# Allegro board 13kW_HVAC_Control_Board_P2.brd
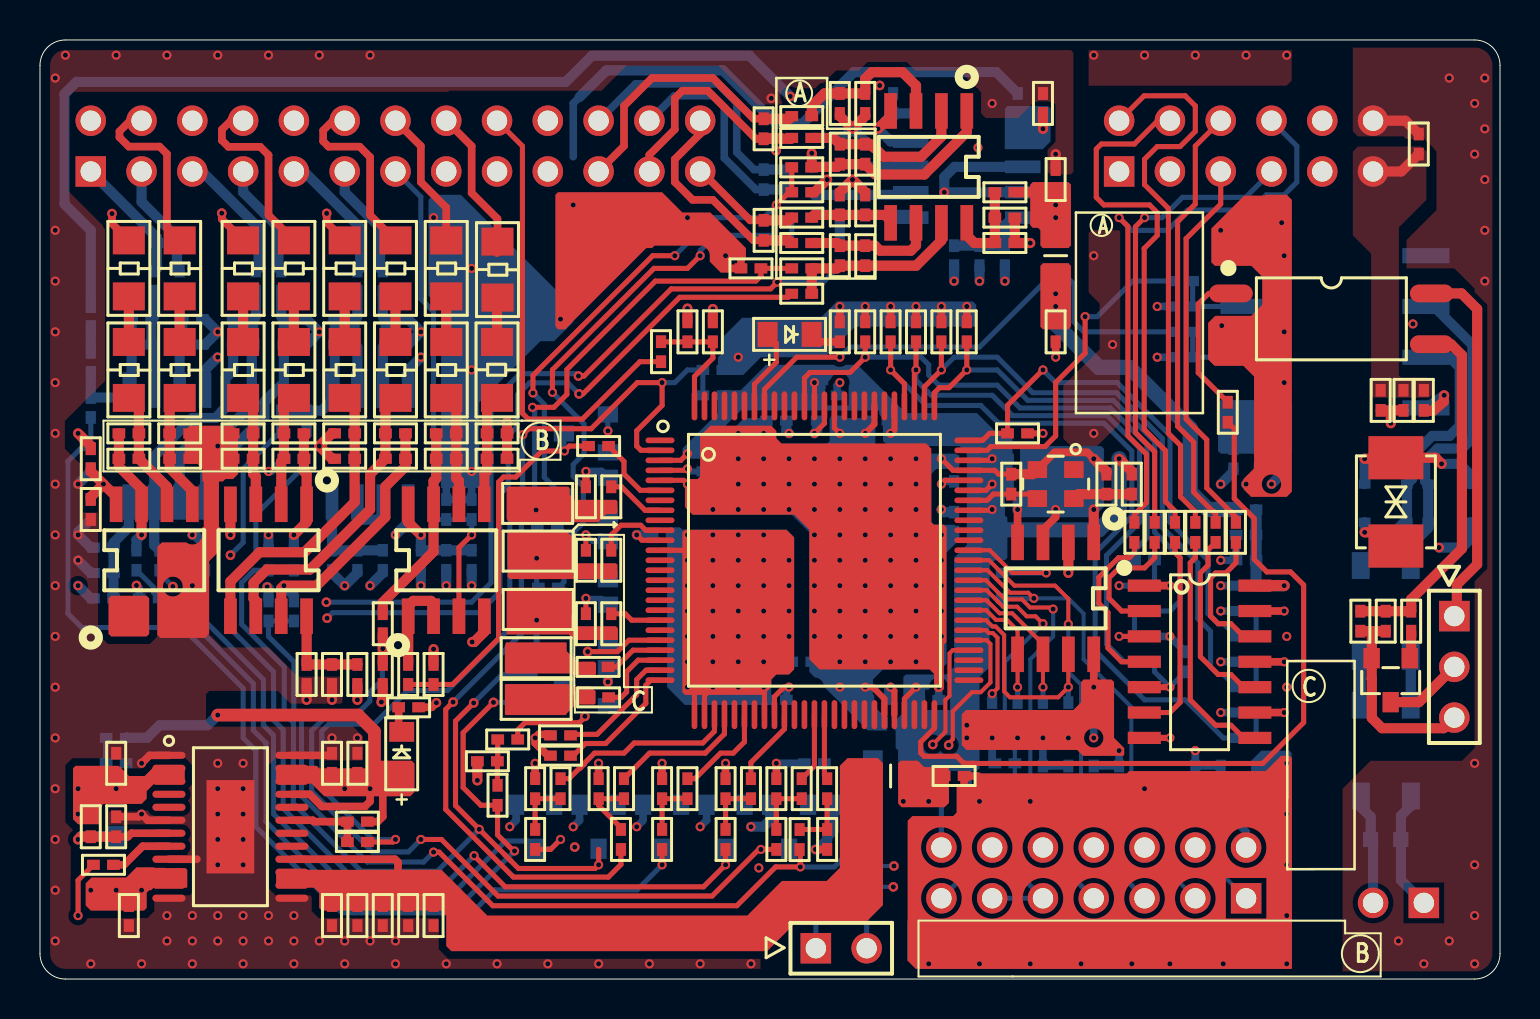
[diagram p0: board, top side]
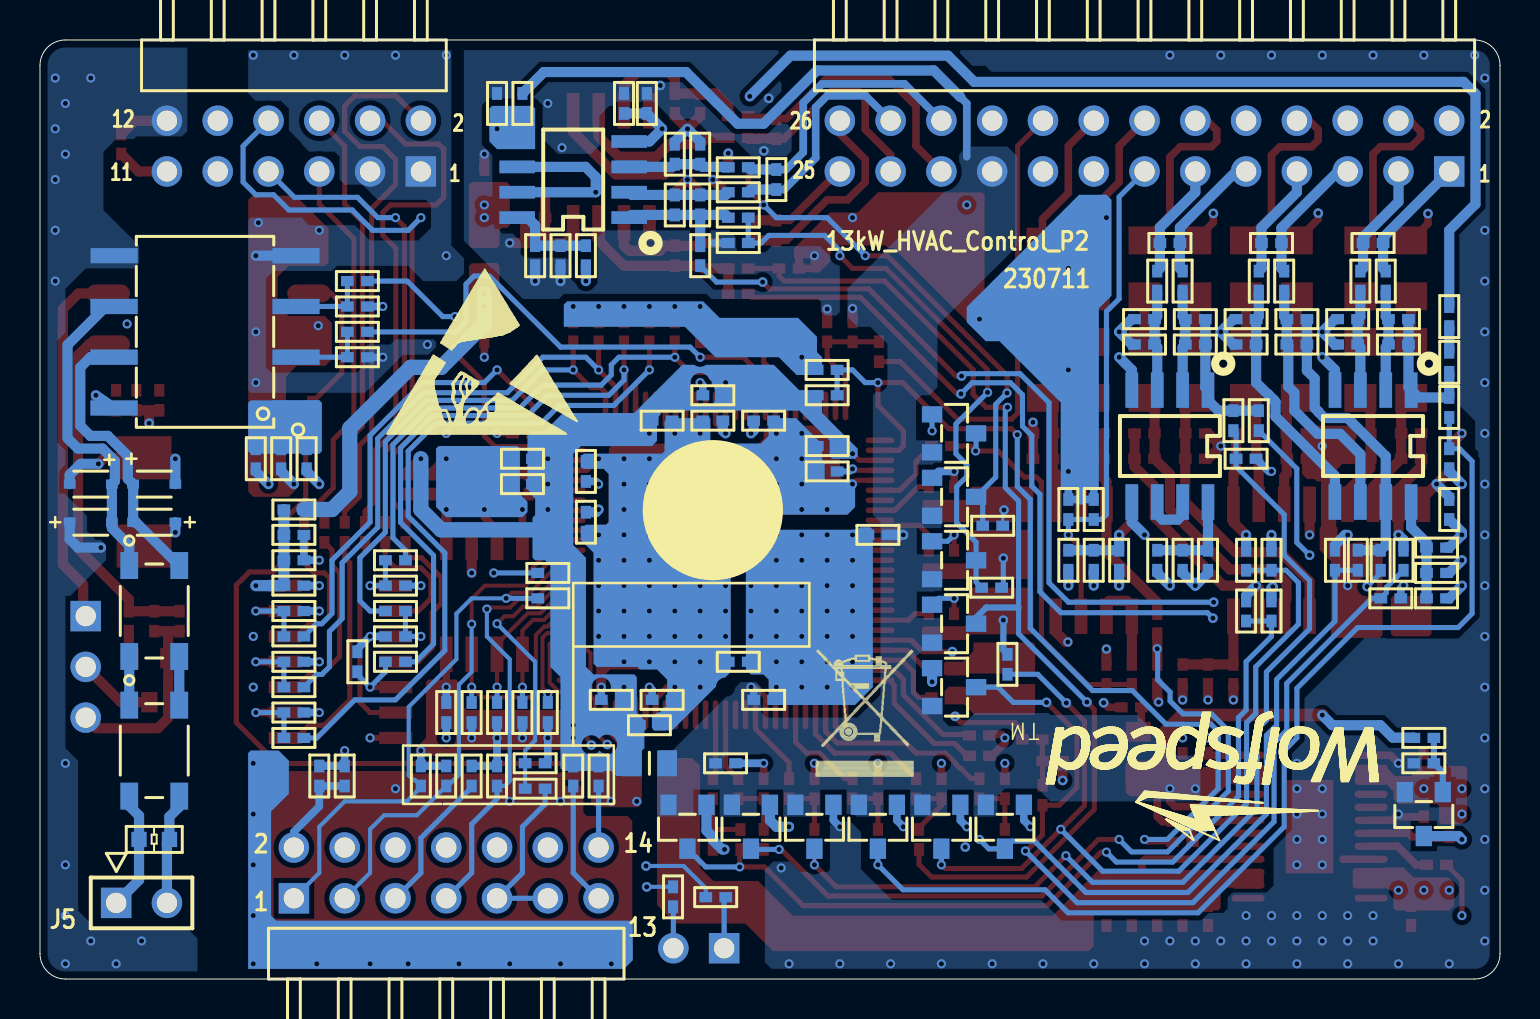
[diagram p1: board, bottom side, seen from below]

Outline 73.03 x 46.99 mm; copper layers: TOP, GND02, GND03, BOTTOM. Coordinates in mm from the lower left corner of the outline.
Outline path: 0,45.72 arc(0.37,46.62) 1.27,46.99 71.75,46.99 arc(72.65,46.62) 73.03,45.72 73.03,1.27 arc(72.65,0.37) 71.75,0 1.27,0 arc(0.37,0.37) 0,1.27 0,45.72

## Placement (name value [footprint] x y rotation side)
C1  10u  [C0402]  45.72 22.86 90 bottom
C2  10u  [C0402]  36.83 27.94 0 bottom
C3  0.1u  [C0402]  39.37 27.94 180 bottom
C4  0.1u  [C0402]  33.66 25.4 180 bottom
C5  0.1u  [C0402]  41.91 13.97 0 bottom
C6  0.1u  [C0402]  45.72 25.4 270 bottom
C7  2.2u  [C0402]  31.11 22.23 0 bottom
C8  2.2u  [C0402]  36.83 13.97 180 bottom
C9  10u  [C0402]  39.37 29.21 0 bottom
C10  0.1u  [C0402]  33.66 26.67 0 bottom
C11  0.1u  [C0402]  41.91 27.94 180 bottom
C12  0.1u  [C0402]  48.9 24.77 0 bottom
C13  0.1u  [C0402]  44.45 13.97 0 bottom
C14  2.2u  [C0402]  48.9 26.04 0 bottom
C15  22n  [C0402]  33.66 30.48 0 bottom
C16  0.1u  [C0402]  14.61 10.79 90 top
C17  10u  [C0402]  15.88 10.79 90 top
C18  10u  [C0402]  14.61 3.17 270 top
C19  0.1u  [C0402]  59.05 10.16 270 bottom
C20  10u  [C0402]  15.88 3.17 270 top
C21  0.1u  [C0402]  18.41 3.17 270 top
C22  0.1u  [C0402]  17.14 3.17 270 top
C23  10u  [C0402]  4.45 3.17 270 top
C24  10u  [C0402]  3.81 10.8 90 top
C25  0.1u  [C0402]  3.81 7.62 90 top
C26  0.1u  [C0402]  52.7 13.34 270 bottom
C27  2.2u  [C0402]  53.34 24.77 90 top
C28  22p  [C0402]  48.58 24.77 90 top
C29  10u  [C0402]  42.55 12.7 180 bottom
C30  10u  [C0402]  19.68 3.17 270 top
C31  10u  [C0402]  38.73 10.79 180 bottom
C32  0.1u  [C0402]  45.72 10.16 0 top
C33  10u  [C0402]  50.8 40.01 90 top
C34  10u  [C0402]  50.8 32.38 270 top
C35  120p  [C0402]  67.31 17.91 270 top
C36  0.1u  [C0402]  3.17 21.59 180 bottom
C37  2.2n  [C0402]  2.54 26.04 270 bottom
C38  330p  [C0402]  5.08 31.75 0 bottom
C39  2.2n  [C0402]  8.26 20.95 90 bottom
C40  330p  [C0402]  10.16 33.02 0 bottom
C41  2.2n  [C0402]  17.14 15.24 270 top
C42  330p  [C0402]  22.86 26.04 180 top
C43  330p  [C0402]  20.32 26.04 0 top
C44  330p  [C0402]  7.62 31.75 180 bottom
C45  330p  [C0402]  12.7 31.75 180 bottom
C46  1u  [C0402]  20.32 23.5 270 bottom
C47  0.01u  [C0402]  19.68 15.24 90 top
C48  330p  [C0402]  15.24 31.75 0 bottom
C49  2.2n  [C0402]  12.7 26.04 180 bottom
C50  0.1u  [C0402]  14.61 20.95 270 bottom
C51  330p  [C0402]  17.78 31.75 180 bottom
C52  0.47u  [C0402]  50.16 43.81 90 top
C53  0.1u  [C0402]  2.54 23.5 270 bottom
C54  330p  [C0402]  6.99 26.04 180 top
C55  0.01u  [C0402]  68.2 28.96 270 top
C56  2.2n  [C0402]  5.46 19.05 180 bottom
C57  0.1u  [C0402]  67.06 28.96 270 top
C58  1u  [C0402]  68.96 41.78 90 top
C59  330p  [C0402]  4.45 26.04 180 top
C60  0.1u  [C0402]  60.96 26.04 90 bottom
C61  1u  [C0402]  59.69 26.04 90 bottom
C62  330p  [C0402]  10.16 26.04 0 top
C63  2.2n  [C0402]  11.43 20.95 90 bottom
C64  120p  [C0402]  57.15 31.11 180 bottom
C65  120p  [C0402]  57.15 33.66 180 bottom
C66  330p  [C0402]  12.7 26.04 0 top
C67  330p  [C0402]  15.24 26.04 0 top
C68  0.1u  [C0402]  14.61 15.24 270 top
C69  2.2n  [C0402]  11.43 18.41 90 bottom
C70  330p  [C0402]  17.78 26.04 0 top
C71  NA  [C0402]  60.33 13.34 180 bottom
C72  NA  [C0402]  60.33 15.88 180 bottom
C73  NA  [C0402]  60.33 18.41 180 bottom
C74  NA  [C0402]  55.24 19.68 180 bottom
C75  NA  [C0402]  55.24 17.14 0 bottom
C76  NA  [C0402]  57.15 15.88 90 bottom
C77  1u  [C0402]  60.33 19.68 180 bottom
C78  0.1u  [C0402]  60.33 22.23 180 bottom
C79  0.01u  [C0402]  60.33 20.95 180 bottom
C80  2.2n  [C0402]  36.83 9.53 90 top
C81  NA  [C0402]  27.3 20.95 90 top
C82  2.2u  [C0402]  26.04 12.19 180 top
C83  2.2u  [C0402]  26.04 11.18 180 top
C84  2.2n  [C0402]  22.38 10.9 180 top
C85  NA  [C0402]  27.94 9.53 90 top
C86  2.2n  [C0402]  27.3 17.78 90 top
C87  2.2n  [C0402]  39.37 6.99 270 top
C88  NA  [C0402]  27.3 24.13 90 top
C89  4.7u  [C0402]  20.32 20.95 270 bottom
C90  330p  [C0402]  33.66 32.38 90 top
C91  4.7u  [C0402]  3.17 20.32 0 bottom
C92  4.7u  [C0402]  15.88 20.95 270 bottom
C93  4.7u  [C0402]  2.54 23.5 270 top
C94  47p  [C0402]  41.27 43.81 90 top
C95  220p  [C0402]  38.1 39.37 180 top
C96  47p  [C0402]  41.27 41.27 270 top
C97  0.1u  [C0402]  48.26 36.83 0 top
C98  47p  [C0402]  40.01 38.73 270 top
C99  4.7u  [C0402]  48.26 38.1 0 top
C100  220p  [C0402]  35.56 35.56 0 top
C101  47p  [C0402]  41.27 36.2 270 top
C102  0.1u  [C0402]  46.99 36.2 270 bottom
C103  47p  [C0402]  41.27 41.27 270 bottom
C104  4.7u  [C0402]  13.34 15.24 270 top
C105  4.7u  [C0402]  48.26 36.2 270 bottom
C106  220p  [C0402]  38.1 36.83 180 bottom
C107  47p  [C0402]  41.27 38.73 270 bottom
C108  2.2n  [C0402]  34.29 9.53 90 top
C109  2.2n  [C0402]  24.77 9.53 90 top
C110  2.2n  [C0402]  31.11 9.53 90 top
C111  0.1u  [C0402]  43.81 43.81 90 bottom
C112  0.1u  [C0402]  42.67 43.81 270 bottom
C113  0.1u  [C0402]  19.05 20.95 270 bottom
D1  SML-211UTT86  [LED0805]  37.49 32.26 0 top
D2  SML-211UTT86  [LED0805]  18.09 11.27 90 top
D3  BAS21WS-TP  [DIOD-SOD323-2-A_V]  67.31 24.77 180 bottom
D4  BAS21WS-TP  [DIOD-SOD323-2-A_V]  70.48 24.77 0 bottom
D5  BAS21WS-TP  [DIOD-SOD323-2-A_V]  67.31 22.86 0 bottom
D6  BAS21WS-TP  [DIOD-SOD323-2-A_V]  70.48 22.86 180 bottom
D7  SMBJ15CA  [DO214AA]  67.82 23.88 270 top
D8  BAV99-TP  [SOT-23-3]  27.3 27.3 270 bottom
D9  BAV99-TP  [SOT-23-3]  27.3 14.61 270 bottom
D10  BAV99-TP  [SOT-23-3]  27.94 7.62 0 bottom
D11  BAV99-TP  [SOT-23-3]  40.64 7.62 0 bottom
D12  BAV99-TP  [SOT-23-3]  31.12 7.62 0 bottom
D13  BAV99-TP  [SOT-23-3]  24.77 7.62 0 bottom
D14  BAV99-TP  [SOT-23-3]  34.29 7.62 0 bottom
D15  BAV99-TP  [SOT-23-3]  37.47 7.62 0 bottom
D16  BAV99-TP  [SOT-23-3]  27.3 24.13 270 bottom
D17  BAV99-TP  [SOT-23-3]  27.3 17.78 270 bottom
D18  BAV99-TP  [SOT-23-3]  27.3 20.95 270 bottom
DACA  Test point  [TEST_270X100_SMT]  24.82 14 0 top
DACB  Test point  [TEST_270X100_SMT]  24.82 16.08 0 top
IC1  -  [TCLT1003]  64.59 33.04 0 top
IU  Test point  [TEST_270X100_SMT]  24.89 23.8 0 top
IV  Test point  [TEST_270X100_SMT]  24.92 18.49 0 top
IW  Test point  [TEST_270X100_SMT]  24.92 21.41 0 top
J1  2*13P  [HDR2X13H-254MM-90-OP]  17.78 41.68 0 bottom
J2  2*6P  [HDR2X6H-254MM-90-OP]  60.33 41.68 0 bottom
J3  Header 3  [HDR1X3-254MM]  70.74 15.62 270 top
J4  JTAG  [HDR2X7H-254MM-90]  52.7 5.31 180 bottom
J5  CAN  [HDR1X2H-254MM]  67.94 3.81 180 top
J6  SCI  [HDR1X2H-254MM]  40.08 1.54 0 top
L1  BLM21PG221SN1D  [6-0805_L]  42.55 10.79 0 bottom
L2  BLM21PG221SN1D  [6-0805_L]  50.8 36.2 270 top
L3  BLM21PG221SN1D  [6-0805_L]  42.55 10.16 0 top
NOREF  -  []  0 1.57 0 top
NOREF#2  -  []  -4.79 0 90 top
NOREF#3  -  []  75.44 239.4 90 top
NOREF#4  -  []  231.71 47.71 0 top
NOREF#5  -  []  0 240.03 90 top
NOREF#6  -  []  -3.16 0 90 top
NOREF#7  -  []  151.56 239.13 90 top
NOREF#8  -  []  372.11 -26.07 0 top
NOREF#9  -  []  -7 4.11 0 top
NOREF#10  -  []  50.8 30.48 180 bottom
NOREF#11  -  []  31.75 13.94 180 bottom
NOREF#12  -  []  39.37 23.46 180 bottom
Q1  2N7002  [SOT-23-3]  3.81 8.26 0 bottom
Q2  FMMTL619TA  [SOT-23-3]  67.56 14.96 180 top
R1  2k  [0402]  42.55 32.38 270 top
R2  2k  [0402]  43.81 32.38 270 top
R3  2k  [0402]  45.09 32.38 270 top
R4  2k  [0402]  46.35 32.38 270 top
R5  2k  [0402]  48.9 27.3 180 top
R6  2k  [0402]  41.27 32.38 270 top
R7  2k  [0402]  47.62 20.32 180 bottom
R8  2k  [0402]  47.62 13.34 270 bottom
R9  10k  [0402]  33.66 29.21 0 bottom
R10  2k  [0402]  47.62 19.05 180 bottom
R11  10K  [0402]  2.54 7.62 90 top
R12  100K  [0402]  15.88 7.87 180 top
R13  0  [0402]  15.88 6.86 180 top
R14  0  [0402]  3.17 5.71 0 top
R15  1.5K  [0402]  3.81 12.06 0 bottom
R16  0  [0402]  57.78 10.16 270 bottom
R17  10k  [0402]  53.98 10.16 90 bottom
R18  12K  [0402]  3.81 10.79 180 bottom
R19  10k  [0402]  52.7 10.16 90 bottom
R20  0  [0402]  51.44 10.16 90 bottom
R21  10k  [0402]  50.16 10.16 90 bottom
R22  10k  [0402]  48.26 10.79 180 bottom
R23  2k  [0402]  45.09 10.16 270 bottom
R24  0  [0402]  48.26 9.53 0 bottom
R25  2k  [0402]  46.35 10.16 270 bottom
R26  10  [0402]  54.61 24.77 270 top
R27  2k  [0402]  40.01 32.38 270 top
R28  2k  [0402]  18.44 13.6 180 top
R29  0  [0402]  38.1 15.88 180 bottom
R30  10k  [0402]  48.9 13.34 270 bottom
R31  10k  [0402]  50.16 13.34 270 bottom
R32  10k  [0402]  51.44 13.34 270 bottom
R33  510  [0402]  59.41 28.36 90 top
R34  1k  [0402]  68.58 17.91 270 top
R35  20k  [0402]  66.04 17.91 90 top
R36  2k  [0402]  39.23 4.1 180 bottom
R37  2k  [0402]  41.36 4.11 270 bottom
R38  100  [0402]  31.06 31.39 90 top
R39  12k  [R1206]  22.86 30.48 270 top
R40  2k  [0402]  5.08 33.02 180 bottom
R41  12k  [0402]  22.86 27.3 0 top
R42  2k  [0402]  5.71 34.92 270 bottom
R43  2k  [0402]  10.16 31.75 180 bottom
R44  NA  [0402]  6.35 36.83 180 bottom
R45  12k  [0402]  20.32 27.3 180 top
R46  2k  [0402]  10.79 34.92 270 bottom
R47  0  [R1206]  20.32 35.56 90 top
R48  12k  [R1206]  20.32 30.48 90 top
R49  2k  [0402]  6.99 34.92 270 bottom
R50  NA  [0402]  11.43 36.83 180 bottom
R51  2k  [0402]  7.62 33.02 0 bottom
R52  2k  [0402]  12.06 34.92 270 bottom
R53  2k  [0402]  12.7 33.02 0 bottom
R54  100  [0402]  18.41 15.24 270 top
R55  1k  [0402]  38.1 42.09 180 top
R56  2k  [0402]  21.59 23.5 270 bottom
R57  2k  [0402]  15.24 33.02 180 bottom
R58  1k  [0402]  13.34 27.94 90 bottom
R59  2k  [0402]  15.88 34.92 270 bottom
R60  10  [0402]  17.14 20.95 270 bottom
R61  NA  [0402]  16.51 36.83 180 bottom
R62  2k  [0402]  17.14 34.92 270 bottom
R63  2k  [0402]  17.78 33.02 0 bottom
R64  NA  [0402]  2.54 30.86 270 bottom
R65  NA  [0402]  5.97 20.95 90 bottom
R66  10  [0402]  2.54 26.04 90 top
R67  1k  [0402]  4.83 20.95 90 bottom
R68  5k  [0402]  6.99 27.3 0 top
R69  100k  [R1206]  6.99 35.56 90 top
R70  5k  [R1206]  6.99 30.48 90 top
R71  100k  [R1206]  4.45 35.56 90 top
R72  5k  [R1206]  4.45 30.48 90 top
R73  10  [0402]  62.23 26.04 90 bottom
R74  5k  [0402]  4.45 27.3 0 top
R75  0  [0402]  69.22 28.96 270 top
R76  1k  [0402]  12.7 20.95 90 bottom
R77  5k  [0402]  10.16 27.3 180 top
R78  100k  [R1206]  10.16 35.56 90 top
R79  5k  [R1206]  10.16 30.48 90 top
R80  1k  [0402]  57.15 32.38 0 bottom
R81  120  [R0603]  67.31 6.99 0 bottom
R82  1k  [0402]  57.15 34.92 0 bottom
R83  100k  [R1206]  12.7 35.56 90 top
R84  5k  [R1206]  12.7 30.48 90 top
R85  5k  [0402]  12.7 27.3 180 top
R86  10  [0402]  15.88 15.24 270 top
R87  1k  [0402]  12.7 18.41 90 bottom
R88  5k  [0402]  15.24 27.3 180 top
R89  100k  [R1206]  15.24 35.56 90 top
R90  5k  [R1206]  15.24 30.48 90 top
R91  100k  [R1206]  17.78 35.56 90 top
R92  5k  [R1206]  17.78 30.48 90 top
R93  5k  [0402]  17.78 27.3 180 top
R94  68  [0402]  57.78 22.35 90 top
R95  68  [0402]  56.77 22.35 270 top
R96  1k  [0402]  60.33 12.06 0 bottom
R97  68  [0402]  58.8 22.35 90 top
R98  1k  [0402]  55.24 15.88 0 bottom
R99  1k  [0402]  60.33 14.61 0 bottom
R100  68  [0402]  54.74 22.35 270 top
R101  1k  [0402]  55.24 18.41 180 bottom
R102  68  [0402]  59.82 22.35 90 top
R103  1k  [0402]  60.33 17.14 0 bottom
R104  68  [0402]  55.75 22.35 270 top
R105  1k  [0402]  55.24 20.95 180 bottom
R106  330  [0402]  38.1 40.62 180 top
R107  18k  [0402]  40.01 43.81 270 top
R108  NA  [0402]  36.2 42.55 90 top
R109  10  [0402]  60.33 23.5 0 bottom
R110  2K  [0402]  32.38 32.38 90 top
R111  1k  [0402]  38.1 43.18 180 top
R112  NA  [0402]  36.2 37.47 90 top
R113  NA  [0402]  36.2 40.01 90 bottom
R114  100  [0402]  35.56 9.53 270 top
R115  0  [0402]  25.43 19.58 0 bottom
R116  100  [0402]  28.57 20.95 270 top
R117  100  [0402]  27.94 26.67 180 top
R118  100  [0402]  38.1 9.53 270 top
R119  1k  [0402]  36.83 6.99 270 top
R120  100  [0402]  28.57 24.13 270 top
R121  0  [0402]  25.37 22.68 0 bottom
R122  100  [0402]  39.37 9.53 270 top
R123  1k  [0402]  37.99 6.98 270 top
R124  100  [0402]  28.57 17.78 270 top
R125  1k  [0402]  24.64 15.75 270 bottom
R126  0  [0402]  29.06 6.99 270 top
R127  100  [0402]  29.21 9.53 270 top
R128  1k  [0402]  22.89 9.19 270 top
R129  100  [0402]  23.39 11.99 180 top
R130  NA  [0402]  12.06 27.94 90 bottom
R131  NA  [0402]  2.54 33.15 270 bottom
R132  NA  [0402]  38.1 34.29 0 top
R133  2k  [0402]  48.9 43.81 90 bottom
R134  NA  [0402]  40.01 36.2 90 bottom
R135  2k  [0402]  50.16 43.81 270 bottom
R136  18k  [0402]  40.01 41.27 90 top
R137  10  [0402]  48.26 39.37 0 top
R138  330  [0402]  38.1 35.56 180 top
R139  18k  [0402]  41.27 38.73 90 top
R140  100  [0402]  27.94 14.1 180 top
R141  1k  [0402]  38.1 38.1 180 top
R142  100  [0402]  27.91 15.62 180 top
R143  1k  [0402]  38.1 36.83 180 top
R144  18k  [0402]  40.01 36.2 90 top
R145  10  [0402]  45.72 36.2 270 bottom
R146  330  [0402]  38.1 38.1 180 bottom
R147  18k  [0402]  40.01 41.27 90 bottom
R148  10  [0402]  21.59 20.95 270 bottom
R149  1k  [0402]  38.1 40.62 180 bottom
R150  10  [0402]  3.17 19.05 180 bottom
R151  1k  [0402]  38.1 39.37 180 bottom
R152  18k  [0402]  40.01 38.73 90 bottom
R153  1k  [0402]  2.54 28.6 90 bottom
R154  1k  [0402]  31.11 6.99 90 top
R155  100  [0402]  32.38 9.53 90 top
R156  1k  [0402]  34.29 6.99 270 top
R157  1k  [0402]  24.77 6.99 90 top
R158  100  [0402]  26.04 9.53 90 top
R159  1k  [0402]  7.11 20.95 90 bottom
R160  1k  [0402]  17.14 17.78 270 top
R161  0  [R1206]  22.88 35.5 90 top
T1  DLW43SH101XK2L  [T1-1812]  67.31 18.41 270 bottom
T2  DLW43SH101XK2L  [T1-1812]  67.31 11.43 270 bottom
U1  F280049CPZS  [PZ0100A_N]  38.73 20.95 0 top
U2  -  [TPS70445PWP]  9.53 7.62 0 top
U3  24LC16BT-I/SN  [8SOIC]  50.8 19.05 270 top
U4  OPA2376AQDRQ1  [8SOIC]  20.32 20.95 90 top
U5  OPA2376AQDRQ1  [8SOIC]  6.35 26.67 270 bottom
U6  OPA2376AQDRQ1  [8SOIC]  16.51 26.67 270 bottom
U7  OPA2376AQDRQ1  [8SOIC]  5.71 20.95 90 top
U8  OPA2376AQDRQ1  [8SOIC]  11.43 20.96 270 top
U9  ISO1050DUBR  [8-SOP]  64.77 32.38 0 bottom
U10  MC74VHCT50ADR2G  [14SOIC]  58 15.88 0 top
U11  OPA2836IDR  [8SOIC]  44.45 40.64 270 top
U12  OPA2836IDR  [8SOIC]  46.35 40.01 0 bottom
Y1  20MHz  [TBD-FOOTPRINT-1]  50.8 24.77 180 top

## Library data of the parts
C1-C113 = C0402: User Part Number: HAMP; Tolerance: #TOL
D1 D2 = LED0805: Tolerance: #TOL; User Part Number: HAMP
D3-D6 = DIOD-SOD323-2-A_V: User Part Number: HAMP; Tolerance: #TOL
D7 = DO214AA: User Part Number: HAMP; Tolerance: #TOL
D8-D18 Q1 Q2 = SOT-23-3: User Part Number: HAMP; Tolerance: #TOL
DACA DACB IU IV IW = TEST_270X100_SMT: User Part Number: HAMP; Tolerance: #TOL
IC1 = TCLT1003: Tolerance: #TOL; User Part Number: HAMP
J1 = HDR2X13H-254MM-90-OP: User Part Number: HAMP; Tolerance: #TOL
J2 = HDR2X6H-254MM-90-OP: Tolerance: #TOL; User Part Number: HAMP
J3 = HDR1X3-254MM: Tolerance: #TOL; User Part Number: HAMP
J4 = HDR2X7H-254MM-90: Tolerance: #TOL; User Part Number: HAMP
J5 J6 = HDR1X2H-254MM: User Part Number: HAMP; Tolerance: #TOL
L1-L3 = 6-0805_L: User Part Number: HAMP; Tolerance: #TOL
R1-R38 R40-R46 R49-R68 R73-R77 R80 R82 R85-R88 R93-R160 = 0402: Tolerance: #TOL; User Part Number: HAMP
R39 R47 R48 R69-R72 R78 R79 R83 R84 R89-R92 R161 = R1206: Tolerance: #TOL; User Part Number: HAMP
R81 = R0603: User Part Number: HAMP; Tolerance: #TOL
T1 T2 = T1-1812: User Part Number: HAMP; Tolerance: #TOL
U1 = PZ0100A_N: User Part Number: HAMP; Tolerance: #TOL
U2 = TPS70445PWP: User Part Number: HAMP; Tolerance: #TOL
U3-U8 U11 U12 = 8SOIC: User Part Number: HAMP; Tolerance: #TOL
U9 = 8-SOP: User Part Number: HAMP; Tolerance: #TOL
U10 = 14SOIC: User Part Number: HAMP; Tolerance: #TOL
Y1 = TBD-FOOTPRINT-1: User Part Number: HAMP; Tolerance: #TOL

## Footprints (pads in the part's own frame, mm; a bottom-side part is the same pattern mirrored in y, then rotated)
6-0805_L
  rect 0.991x1.295 smd: 1(-0.889,0) 2(0.889,0)
8-SOP
  rect 2.362x0.762 smd: 1(-4.55,3.81) 2(-4.55,1.27) 3(-4.55,-1.27) 4(-4.55,-3.81) 5(4.55,-3.81) 6(4.55,-1.27) 7(4.55,1.27) 8(4.55,3.81)
8SOIC
  rect 1.778x0.635 smd: 1(-2.8,1.905) 2(-2.8,0.635) 3(-2.8,-0.635) 4(-2.8,-1.905) 5(2.8,-1.905) 6(2.8,-0.635) 7(2.8,0.635) 8(2.8,1.905)
14SOIC
  rect 1.651x0.61 smd: 1(-2.765,3.81) 2(-2.765,2.54) 3(-2.765,1.27) 4(-2.765,0) 5(-2.765,-1.27) 6(-2.765,-2.54) 7(-2.765,-3.81) 8(2.765,-3.81) 9(2.765,-2.54) 10(2.765,-1.27) 11(2.765,0) 12(2.765,1.27) 13(2.765,2.54) 14(2.765,3.81)
0402
  rect 0.635x0.508 smd: 1(-0.5,0) 2(0.5,0)
C0402
  rect 0.635x0.508 smd: 1(-0.5,0) 2(0.5,0)
DIOD-SOD323-2-A_V
  rect 0.584x0.457 smd: 1(-1.055,0) 2(1.055,0)
DO214AA
  rect 2.159x2.743 smd: 1(2.21,0) 2(-2.21,0)
HDR1X2H-254MM
  rect 1.524x1.524 hole 1.016: 1(-1.27,0)
  round 1.524 hole 1.016: 2(1.27,0)
HDR1X3-254MM
  rect 1.524x1.524 hole 1.016: 1(-2.54,0)
  round 1.524 hole 1.016: 2(0,0) 3(2.54,0)
HDR2X6H-254MM-90-OP
  rect 1.524x1.524 hole 1.016: 1(-6.35,1.27)
  round 1.524 hole 1.016: 2(-6.35,-1.27) 3(-3.81,1.27) 4(-3.81,-1.27) 5(-1.27,1.27) 6(-1.27,-1.27) 7(1.27,1.27) 8(1.27,-1.27) 9(3.81,1.27) 10(3.81,-1.27) 11(6.35,1.27) 12(6.35,-1.27)
HDR2X7H-254MM-90
  rect 1.524x1.524 hole 1.016: 1(-7.62,-1.27)
  round 1.524 hole 1.016: 2(-7.62,1.27) 3(-5.08,-1.27) 4(-5.08,1.27) 5(-2.54,-1.27) 6(-2.54,1.27) 7(0,-1.27) 8(0,1.27) 9(2.54,-1.27) 10(2.54,1.27) 11(5.08,-1.27) 12(5.08,1.27) 13(7.62,-1.27) 14(7.62,1.27)
HDR2X13H-254MM-90-OP
  rect 1.524x1.524 hole 1.016: 1(-15.24,1.27)
  round 1.524 hole 1.016: 2(-15.24,-1.27) 3(-12.7,1.27) 4(-12.7,-1.27) 5(-10.16,1.27) 6(-10.16,-1.27) 7(-7.62,1.27) 8(-7.62,-1.27) 9(-5.08,1.27) 10(-5.08,-1.27) 11(-2.54,1.27) 12(-2.54,-1.27) 13(0,1.27) 14(0,-1.27) 15(2.54,1.27) 16(2.54,-1.27) 17(5.08,1.27) 18(5.08,-1.27) 19(7.62,1.27) 20(7.62,-1.27) 21(10.16,1.27) 22(10.16,-1.27) 23(12.7,1.27) 24(12.7,-1.27) 25(15.24,1.27) 26(15.24,-1.27)
LED0805
  rect 0.991x1.245 smd: 1(-1.1,0) 2(1.1,0)
PZ0100A_N
  oval 1.448x0.279 smd: 1(-7.725,6) 2(-7.725,5.5) 3(-7.725,5) 4(-7.725,4.5) 5(-7.725,4) 6(-7.725,3.5) 7(-7.725,3) 8(-7.725,2.5) 9(-7.725,2) 10(-7.725,1.5) 11(-7.725,1) 12(-7.725,0.5) 13(-7.725,0) 14(-7.725,-0.5) 15(-7.725,-1) 16(-7.725,-1.5) 17(-7.725,-2) 18(-7.725,-2.5) 19(-7.725,-3) 20(-7.725,-3.5) 21(-7.725,-4) 22(-7.725,-4.5) 23(-7.725,-5) 24(-7.725,-5.5) 25(-7.725,-6) 51(7.725,-6) 52(7.725,-5.5) 53(7.725,-5) 54(7.725,-4.5) 55(7.725,-4) 56(7.725,-3.5) 57(7.725,-3) 58(7.725,-2.5) 59(7.725,-2) 60(7.725,-1.5) 61(7.725,-1) 62(7.725,-0.5) 63(7.725,0) 64(7.725,0.5) 65(7.725,1) 66(7.725,1.5) 67(7.725,2) 68(7.725,2.5) 69(7.725,3) 70(7.725,3.5) 71(7.725,4) 72(7.725,4.5) 73(7.725,5) 74(7.725,5.5) 75(7.725,6)
  oval 0.279x1.448 smd: 26(-6,-7.725) 27(-5.5,-7.725) 28(-5,-7.725) 29(-4.5,-7.725) 30(-4,-7.725) 31(-3.5,-7.725) 32(-3,-7.725) 33(-2.5,-7.725) 34(-2,-7.725) 35(-1.5,-7.725) 36(-1,-7.725) 37(-0.5,-7.725) 38(0,-7.725) 39(0.5,-7.725) 40(1,-7.725) 41(1.5,-7.725) 42(2,-7.725) 43(2.5,-7.725) 44(3,-7.725) 45(3.5,-7.725) 46(4,-7.725) 47(4.5,-7.725) 48(5,-7.725) 49(5.5,-7.725) 50(6,-7.725) 76(6,7.725) 77(5.5,7.725) 78(5,7.725) 79(4.5,7.725) 80(4,7.725) 81(3.5,7.725) 82(3,7.725) 83(2.5,7.725) 84(2,7.725) 85(1.5,7.725) 86(1,7.725) 87(0.5,7.725) 88(0,7.725) 89(-0.5,7.725) 90(-1,7.725) 91(-1.5,7.725) 92(-2,7.725) 93(-2.5,7.725) 94(-3,7.725) 95(-3.5,7.725) 96(-4,7.725) 97(-4.5,7.725) 98(-5,7.725) 99(-5.5,7.725) 100(-6,7.725)
R0603
  rect 0.762x0.762 smd: 1(-0.76,0) 2(0.76,0)
R1206
  rect 1.397x1.6 smd: 1(-1.4,0) 2(1.4,0)
SOT-23-3
  rect 0.813x1.016 smd: 1(-0.95,-1.1) 2(0.95,-1.1) 3(0,1.1)
T1-1812
  rect 1.346x0.889 smd: 1(-2.275,-1.25) 2(2.275,-1.25) 3(2.275,1.25) 4(-2.275,1.25)
TBD-FOOTPRINT-1
  rect 0.965x0.838 smd: 1(-0.913,-0.725) 2(0.913,-0.725) 3(0.913,0.725) 4(-0.913,0.725)
TCLT1003
  oval 2.184x0.889 smd: 1(-5.025,1.27) 2(-5.025,-1.27) 3(5.025,-1.27) 4(5.025,1.27)
TEST_270X100_SMT
  rect 3.048x1.524 smd: 1(0,0)
TPS70445PWP
  oval 1.651x0.356 smd: 1(-3.075,3.575) 2(-3.075,2.925) 3(-3.075,2.275) 4(-3.075,1.625) 5(-3.075,0.975) 6(-3.075,0.325) 7(-3.075,-0.325) 8(-3.075,-0.975) 9(-3.075,-1.625) 10(-3.075,-2.275) 11(-3.075,-2.925) 12(-3.075,-3.575) 13(3.075,-3.575) 14(3.075,-2.925) 15(3.075,-2.275) 16(3.075,-1.625) 17(3.075,-0.975) 18(3.075,-0.325) 19(3.075,0.325) 20(3.075,0.975) 21(3.075,1.625) 22(3.075,2.275) 23(3.075,2.925) 24(3.075,3.575)
  rect 2.388x4.674 smd: 25(0,0)

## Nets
AGND: C7.2 C8.2 C16.2 C17.2 C18.2 C20.2 C21.2 C22.2 C23.2 C24.2 C25.2 C30.2 C31.2 C33.2 C36.2 C37.2 C39.2 C41.2 C42.1 C44.1 C45.1 C46.1 C47.2 C49.2 C50.2 C51.1 C52.2 C53.2 C54.1 C56.2 C62.1 C63.2 C67.1 C68.2 C69.2 C80.2 C81.2 C82.2 C83.2 C84.2 C85.2 C86.2 C87.2 C88.2 C89.2 C90.2 C91.1 C92.2 C93.2 C95.1 C97.2 C99.2 C100.1 C102.2 C104.2 C105.2 C106.1 C108.2 C109.2 C110.2 C111.2 C112.1 C113.2 D8.1 D9.1 D10.1 D11.1 D12.1 D13.1 D14.1 D15.1 D16.1 D17.1 D18.1 J1.17 Q1.2 R18.1 R28.1 R29.2 R41.2 R51.2 R53.2 R56.1 R63.2 R68.2 R77.2 R88.2 R135.1 U1.12 U1.26 U1.27 U1.33 U2.1 U2.6 U2.9 U2.12 U2.13 U2.24 U2.25 U4.4 U5.4 U6.4 U6.5 U7.3 U7.4 U8.4
AGND_U: J1.2 R71.2
AGND_V: J1.8 R83.2
AGND_W: J1.12 R91.2
DGND: C1.1 C2.1 C3.1 C4.1 C5.1 C6.1 C9.2 C10.2 C11.2 C12.2 C13.2 C14.2 C15.2 C19.1 C26.2 C27.2 C28.2 C29.2 C32.2 C34.2 C60.1 C61.1 C64.2 C65.2 C71.2 C72.2 C73.2 C74.2 C75.2 C76.2 C77.2 C78.2 C79.2 IC1.2 J2.1 J2.3 J4.4 J4.6 J4.8 J4.10 J4.12 R1.1 R2.1 R3.1 R4.1 R5.1 R6.1 R16.1 R27.1 R29.1 U1.5 U1.45 U1.72 U1.82 U1.86 U3.1 U3.2 U3.3 U3.4 U9.4 U10.7 Y1.2
VIN: C41.1 D15.3 R119.2 R160.2
VIN+: J1.16 R161.2
VIN-: J1.14 R47.2
A_1.2V: C18.1 C20.1 C21.1 C22.1 C30.1 L3.1 U2.14 U2.15 U2.16
A_3.3V: C7.1 C8.1 C16.1 C17.1 C31.1 D2.1 D8.2 D9.2 D10.2 D11.2 D12.2 D13.2 D14.2 D15.2 D16.2 D17.2 D18.2 J1.19 L1.1 R12.1 R15.2 R110.2 R133.2 U1.11 U1.34 U2.21 U2.22 U2.23
CAN+: J5.2 R81.1 T2.3
CAN+5V: C55.1 C57.1 C58.1 J2.11 R75.1
CAN-: J5.1 R81.2 T2.2
CAN_GND: C55.2 C57.2 C58.2 D5.1 D6.1 D7.1 J2.12 U9.5
CANRX: R80.1 U1.93
CANTX: R82.1 U1.74
D_1.2V: C1.2 C2.2 C3.2 C4.2 C5.2 C6.2 C32.1 L3.2 U1.4 U1.46 U1.71 U1.87
D_3.3V: C9.1 C10.1 C11.1 C12.1 C13.1 C14.1 C26.1 C29.1 L1.2 R7.2 R8.2 R9.2 R10.2 R17.2 R19.2 R20.2 R21.2 R22.2 R23.1 R25.1 R26.1 R30.2 R31.2 R32.2 R73.1 U1.3 U1.47 U1.68 U1.70 U1.73 U1.80 U1.88 U3.8
FAULT: J1.18 R38.1
II_U: R64.1 R131.2
II_V: R65.1 R132.1
II_W: R130.1 R134.1
IPH_U: C95.2 D16.3 R106.2 R121.2
IPH_U+: J1.21 R108.2 R111.2
IPH_U-: J1.23 R55.2 R108.1
IPH_V: C100.2 D17.3 R126.2 R138.2
IPH_V+: J1.25 R112.2 R141.2
IPH_V-: J1.26 R112.1 R143.2
IPH_W: C106.2 D18.3 R115.2 R146.2
IPH_W+: J1.22 R113.2 R149.2
IPH_W-: J1.24 R113.1 R151.2
IU: C37.1 D12.3 R153.1 R154.1
IU+: J1.3 R44.1 R49.1
IU-: J1.1 R42.1 R44.2
IV: C39.1 D13.3 R157.1 R159.1
IV+: J1.7 R50.1 R52.1
IV-: J1.5 R46.1 R50.2
IW: C49.1 D14.3 R58.1 R156.2
IW+: J1.11 R61.1 R62.1
IW-: J1.9 R59.1 R61.2
LED_RED: D1.1 U1.94
MCU_X1: C28.1 U1.69 Y1.3
NETC25_1: C25.1 Q1.3 R11.1 U2.7
NETC27_1: C27.1 R26.2 Y1.4
NETC35_1: C35.1 IC1.3 R34.1 R35.2
NETC36_1: C36.1 C91.2 R150.1 U5.8
NETC38_1: C38.1 R40.2 R64.2 R153.2 U5.1
NETC38_2: C38.2 R40.1 R42.2 U5.2
NETC40_1: C40.1 R43.2 R65.2 R159.2 U5.7
NETC40_2: C40.2 R43.1 R46.2 U5.6
NETC42_2: C42.2 R39.2 R41.1 U4.5
NETC43_1: C43.1 R45.2 R160.1 U4.7
NETC43_2: C43.2 R45.1 R48.1 U4.6
NETC44_2: C44.2 R49.2 R51.1 U5.3
NETC45_2: C45.2 R52.2 R53.1 U5.5
NETC48_1: C48.1 R57.2 R58.2 R130.2 U6.1
NETC48_2: C48.2 R57.1 R59.2 U6.2
NETC50_1: C50.1 C92.1 R60.1 U6.8
NETC51_2: C51.2 R62.2 R63.1 U6.3
NETC52_1: C52.1 R133.1 R135.2 U12.5
NETC53_1: C53.1 C93.1 R66.1 U7.8
NETC54_2: C54.2 R68.1 R70.1 U7.5
NETC59_1: C59.1 R72.1 R74.2 U7.6
NETC59_2: C59.2 R67.2 R74.1 U7.7
NETC60_2: C60.2 C61.2 R73.2 U9.1
NETC62_2: C62.2 R77.1 R79.1 U8.3
NETC64_1: C64.1 R80.2 U9.2
NETC65_1: C65.1 R82.2 U9.3
NETC66_1: C66.1 R84.1 R85.2 U8.2
NETC66_2: C66.2 R76.2 R85.1 U8.1
NETC67_2: C67.2 R88.1 R90.1 U8.5
NETC68_1: C68.1 C104.1 R86.1 U8.8
NETC70_1: C70.1 R92.1 R93.2 U8.6
NETC70_2: C70.2 R87.2 R93.1 U8.7
NETC71_1: C71.1 R96.2 U10.9
NETC72_1: C72.1 R99.2 U10.11
NETC73_1: C73.1 R103.2 U10.13
NETC74_1: C74.1 R105.1 U10.1
NETC75_1: C75.1 R101.2 U10.3
NETC76_1: C76.1 R98.2 U10.5
NETC77_1: C77.1 C78.1 C79.1 R109.2 U10.14
NETC80_1: C80.1 R118.2 R119.1
NETC81_1: C81.1 IW.1 R115.1 R116.2
NETC82_1: C82.1 U1.24
NETC83_1: C83.1 U1.25
NETC84_1: C84.1 R128.1 R129.2
NETC85_1: C85.1 R126.1 R127.2
NETC86_1: C86.1 IV.1 R124.2 R125.1
NETC87_1: C87.1 R122.2 R123.1
NETC88_1: C88.1 IU.1 R120.2 R121.1
NETC89_1: C89.1 C113.1 R148.1 U4.8
NETC90_1: C90.1 R38.2 R110.1 U1.100
NETC94_2: C94.2 R107.1 R111.1 U11.3
NETC96_1: C96.1 R55.1 R136.2 U11.2
NETC96_2: C96.2 R106.1 R131.1 R136.1 U11.1
NETC97_1: C97.1 C99.1 R137.1 U11.8
NETC98_2: C98.2 R139.1 R141.1 U11.5
NETC101_1: C101.1 R143.1 R144.2 U11.6
NETC101_2: C101.2 R132.2 R138.1 R144.1 U11.7
NETC102_1: C102.1 C105.1 R145.1 U12.8
NETC103_2: C103.2 R147.1 R149.1 U12.3
NETC107_1: C107.1 R151.1 R152.2 U12.2
NETC107_2: C107.2 R134.2 R146.1 R152.1 U12.1
NETC108_1: C108.1 R114.2 R156.1
NETC109_1: C109.1 R157.2 R158.1
NETC110_1: C110.1 R154.2 R155.1
NETD1_2: D1.2 R27.2
NETD2_2: D2.2 R28.2
NETD3_1: D3.1 D5.2 T1.4 U9.7
NETD3_2: D3.2 D4.2 D7.2
NETD4_1: D4.1 D6.2 T1.1 U9.6
NETDACA_1: DACA.1 R140.2
NETDACB_1: DACB.1 R142.2
NETIC1_1: IC1.1 R33.2
NETJ4_5: J4.5 R20.1
NETJ4_9: J4.9 J4.11 R24.1
NETJ4_13: J4.13 R25.2
NETJ4_14: J4.14 R23.2
NETQ1_1: Q1.1 R15.1 R18.2
NETQ2_1: Q2.1 R34.2
NETR7_1: R7.1 U1.64
NETR8_1: R8.1 U1.56
NETR12_2: R12.2 R13.2 U2.19
NETR14_2: R14.2 U2.8
NETR36_1: R36.1 U1.54
NETR37_1: R37.1 U1.55
NETR39_1: R39.1 R161.1
NETR47_1: R47.1 R48.2
NETR54_1: R54.1 U4.1 U4.2
NETR69_1: R69.1 R70.2
NETR71_1: R71.1 R72.2
NETR75_2: R75.2 U9.8
NETR78_1: R78.1 R79.2
NETR83_1: R83.1 R84.2
NETR89_1: R89.1 R90.2
NETR91_1: R91.1 R92.2
NETR94_1: R94.1 U10.8
NETR95_2: R95.2 U10.6
NETR97_1: R97.1 U10.10
NETR100_2: R100.2 U10.4
NETR102_1: R102.1 U10.12
NETR104_2: R104.2 U10.2
NETR114_1: R114.1 U1.35
NETR116_1: R116.1 U1.10
NETR117_1: R117.1 U1.6
NETR118_1: R118.1 U1.38
NETR120_1: R120.1 U1.8
NETR122_1: R122.1 U1.39
NETR124_1: R124.1 U1.19
NETR127_1: R127.1 U1.29
NETR129_1: R129.1 U1.21
NETR140_1: R140.1 U1.23
NETR142_1: R142.1 U1.22
NETR155_2: R155.2 U1.31
NETR158_2: R158.2 U1.28
NETT1_2: T1.2 T2.1
NETT1_3: T1.3 T2.4
NETU6_6: U6.6 U6.7
NETU7_1: U7.1 U7.2
P_-2.7V: C111.1 C112.2 J1.20 U11.4 U12.4
PWM-1A: J2.2 R94.2
PWM-1AA: R1.2 R96.1 U1.79
PWM-1B: J2.4 R95.1
PWM-1BB: R2.2 R98.1 U1.78
PWM-2A: J2.6 R97.2
PWM-2AA: R3.2 R99.1 U1.77
PWM-2B: J2.8 R100.1
PWM-2BB: R4.2 R101.1 U1.76
PWM-3A: J2.5 R102.2
PWM-3AA: R5.2 R103.1 U1.75
PWM-3B: J2.7 R104.1
PWM-3BB: R6.2 R105.2 U1.89
R_12V: IC1.4 J3.1
R_GND: C35.2 J3.3 Q2.2 R35.1
REF1.65: C94.1 C98.1 C103.1 R107.2 R139.2 R147.2 U12.6 U12.7
RELAY: R33.1 U1.50
RLY: J3.2 Q2.3
SCIA_RX: J6.2 R37.2
SCIA_TX: J6.1 R36.2
SCL: R31.1 U1.59 U3.6
SDA: R30.1 U1.58 U3.5
TCK_P: R22.1 R24.2 U1.60
TDI_P: J4.3 R19.1 U1.63
TDO_P: J4.7 R21.1 U1.61
TEMP: C46.2 J1.13 R56.2 U4.3
TEMP1: C47.1 D8.3 R54.2 R117.2
TMS_P: J4.1 R10.1 R17.1 U1.62
TRST_P: C19.2 J4.2 R16.2
U_SAMPLE: J1.4 R69.2
V_SAMPLE: J1.6 R78.2
VA+5V: C23.1 C24.1 C33.1 J1.15 L2.1 R11.2 R60.2 R66.2 R86.2 R137.2 R145.2 R148.2 R150.2 U2.2 U2.3 U2.10 U2.11
VD+5V: C34.1 L2.2 R109.1
VU: C56.1 D9.3 R67.1 R128.2
VV: C63.1 D10.3 R76.1 R125.2
VW: C69.1 D11.3 R87.1 R123.2
W_SAMPLE: J1.10 R89.2
WP: R32.1 U1.57 U3.7
XRS: C15.1 R9.1 R13.1 R14.1 U1.2

Pads without a net: J2 9 10; U1 1 7 9 13 14 15 16 17 18 20 30 32 36 37 40 41 42 43 44 48 49 51 52 53 65 66 67 81 83 84 85 90 91 92 95 96 97 98 99; U2 4 5 17 18 20; Y1 1

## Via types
v1: diameter 0.483, hole 0.254, TOP to BOTTOM, 40 vias
v2: diameter 0.457, hole 0.254, TOP to BOTTOM, 408 vias

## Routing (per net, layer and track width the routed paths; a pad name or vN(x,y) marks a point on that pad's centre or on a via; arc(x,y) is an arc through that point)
AGND: length 87.8
  TOP w0.254: C81.2 v2(27.3,22.23) ; U1.27 33.23,14.18 v2(33.66,14.61) ; U1.12 32.38,21.46 ; v2(32.38,14.61) 32.74,14.25 U1.26 ; C86.2 v2(27.3,19.05) ; U1.33 36.23,14.57 v2(36.2,14.61)
  TOP w0.381: 35.06,36.2 C100.1 34.36,35.56 ; C83.2 25.4,11.18 24.77,11.81 v2(24.77,12.06) 24.94,12.24 25.48,12.24 C82.2 ; C87.2 v2(38.79,6.48) ; C16.2 14.5,11.19 U2.24 ; C110.2 v2(31.11,10.79) ; U2.1 5.48,11.19 v2(5.08,10.79) ; C80.2 v2(36.83,10.79) ; U2.9 7.85,5.99 ; C88.2 v2(27.3,25.4) ; C85.2 v2(27.94,10.79) ; C109.2 v2(24.77,10.79) ; U2.6 5.39,7.95 v2(5.08,8.26) 4.95,8.12 C25.2 ; v1(19.83,13.83) 19.6,13.6 R28.1 ; C108.2 v2(34.29,10.79)
  TOP w0.508: C47.2 v2(19.68,16.51) ; v2(39.37,40.01) 38.73,39.37 C95.1 ; v2(9.53,22.23) U8.4 ; C104.2 v2(13.34,13.97) ; C90.2 v2(33.66,33.53) ; C84.2 v1(21.88,9.94) ; C42.1 R41.2 v2(23.36,27.86) ; C33.2 v2(50.8,41.27) ; v2(49.53,36.83) C97.2 C99.2 ; U4.4 22.23,17.37 21.72,16.87 v2(21.62,16.87) ; C41.2 17.14,14.09 17.11,14.06 17.11,13.9 v2(17.08,13.86) ; U7.4 v2(7.62,19.68) ; C67.1 14.61,26.04 v2(13.97,26.67) 14.61,27.3 R88.2 ; C68.2 v2(14.61,13.97)
  BOTTOM w0.254: D17.1 28.09,19.05 v2(27.3,19.05) ; v2(27.3,22.23) 27.62,21.91 D18.1 ; D8.1 v2(28.41,27.43)
  BOTTOM w0.381: 20.95,23.99 R56.1 21.59,24.69 ; D13.1 23.82,7.94 v2(23.5,7.62) ; v2(26.67,7.62) 26.99,7.94 D10.1 ; v2(27.3,25.4) 28.08,25.4 D16.1 ; v2(11.43,25.4) 11.56,25.4 C49.2 ; D14.1 33.34,7.94 v2(33.02,7.62) ; C31.2 v2(36.83,10.79) ; 20.95,24 C46.1 20.32,24.69 ; C56.2 4.96,19.56 v1(4.83,19.69) ; D12.1 30.17,7.94 v2(29.84,7.62) ; C106.1 39.3,36.83
  BOTTOM w0.508: R63.2 18.41,33.02 v2(19.05,32.38) 18.41,31.75 C51.1 ; C36.2 2.54,21.59 v2(1.91,22.23) 1.91,22.36 C93.2 ; D15.1 36.52,7.94 36.2,7.62 v2(35.56,7.62) ; C91.1 2.54,20.32 v2(1.91,20.95) ; C44.1 8.26,31.75 v2(8.89,32.38) 8.26,33.02 R51.2 ; v2(7.62,22.23) 7.75,22.23 8.26,21.72 C39.2 ; 8.26,29.47 8.26,30.48 v2(8.89,31.11) ; v2(38.79,6.48) 38.9,6.48 39.37,6.95 39.37,7.11 39.69,7.43 D11.1 ; v2(17.78,22.23) 18.41,22.86 U6.5 ; C113.2 v2(19.05,19.68) ; v2(1.91,24.77) 2.54,25.4 C37.2 ; D9.1 v1(28.41,14.87) ; C92.2 15.88,20.32 v2(15.24,19.68) 14.61,20.32 C50.2 ; R53.2 13.34,33.02 v2(13.97,32.38) 13.34,31.75 C45.1 ; v2(19.05,31.11) 18.41,30.48 U6.4 ; C102.2 v2(46.99,34.92) ; v2(11.36,19.63) 11.43,19.56 C69.2 ; C63.2 v2(11.43,22.23) ; C7.2 v2(32.38,22.23) ; C105.2 v2(48.26,34.92) ; C89.2 v2(20.32,19.68)
  vias: v1(26.75,6.6) v1(36.58,44.07) v1(36.82,41.45) v1(42,44.71) v2(0.76,45.09) v2(0.76,37.47) v2(0.76,34.92) v2(0.76,32.38) v2(0.76,29.84) v2(0.76,27.3) v2(0.76,24.77) v2(0.76,22.23) v2(0.76,19.68) v2(0.76,17.14) v2(0.76,14.61) v2(0.76,12.06) v2(0.76,9.53) v2(0.76,6.99) v2(0.76,4.45) v2(0.76,1.91) v2(1.27,46.23) v2(2.54,0.76) v2(3.81,46.23) v2(5.08,0.76) v2(6.35,46.23) v2(6.35,3.17) v2(6.35,1.91) v2(7.62,3.17) v2(7.62,1.91) v2(7.62,0.76) v2(8.89,46.23) v2(8.89,26.67) v2(8.89,10.79) v2(8.89,9.53) v2(8.89,8.26) v2(8.89,6.99) v2(8.89,5.71) v2(8.89,3.17) v2(8.89,1.91) v2(10.16,10.79) v2(10.16,9.53) v2(10.16,8.26) v2(10.16,6.99) v2(10.16,5.71) v2(10.16,3.17) v2(10.16,1.91) v2(10.16,0.76) v2(11.43,46.23) v2(11.43,3.17) v2(11.43,1.91) v2(12.7,3.17) v2(12.7,1.91) v2(12.7,0.76) v2(13.97,46.23) v2(13.97,1.91) v2(14.61,12.06) v2(15.24,1.91) v2(15.24,0.76) v2(15.88,12.06) v2(16.51,46.23) v2(16.51,1.91) v2(17.78,1.91) v2(17.78,0.76) v2(19.68,38.1) v2(20.32,0.76) v2(21.59,35.56) v2(21.59,30.48) v2(21.59,25.4) v2(22.86,0.76) v2(25.4,0.76) v2(26.04,33.02) v2(26.67,38.73) v2(27.94,0.76) v2(30.48,0.76) v2(32.38,38.1) v2(32.38,20.95) v2(32.38,19.68) v2(32.38,18.41) v2(32.38,17.14) v2(32.38,15.88) v2(33.02,0.76) v2(33.66,22.23) v2(33.66,20.95) v2(33.66,19.68) v2(33.66,18.41) v2(33.66,17.14) v2(33.66,15.88) v2(34.29,36.2) v2(34.92,22.23) v2(34.92,20.95) v2(34.92,19.68) v2(34.92,18.41) v2(34.92,17.14) v2(34.92,15.88) v2(34.92,14.61) v2(35.56,0.76) v2(35.95,5.56) v2(36.2,22.23) v2(36.2,20.95) v2(36.2,19.68) v2(36.2,18.41) v2(36.2,17.14) v2(36.2,15.88) v2(37.47,20.95) v2(37.47,19.68) v2(37.47,18.41) v2(37.47,17.14) v2(46.92,41.6) v2(47.62,43.81)
AGND_U: length 11.4
  TOP w0.381: v1(3.6,38.3) 3.6,37.8 R71.2
  GND02 w0.381: v1(3.6,38.3) 5.54,38.3 6.35,39.12 6.35,41.27 5.97,41.66 4.45,41.66 3.15,42.95 J1.2
AGND_V: length 9.2
  TOP w0.381: R83.2 11.43,38.23 11.43,41.23 11.02,41.64 9.42,41.64 9.1,41.97 9.1,42.51 9.54,42.95 J1.8
AGND_W: length 9.2
  TOP w0.381: J1.12 14.65,42.95 14.16,42.46 14.16,41.92 14.43,41.65 15.99,41.65 16.51,41.13 16.51,38.23 R91.2
DGND: length 52.5
  TOP w0.254: v2(40.01,27.3) 39.73,27.58 U1.86 ; C28.2 47.94,25.27 47.75,25.46 U1.72 45.66,25.46 v2(45.09,26.04) ; U1.5 32.2,24.95 v2(32.38,24.77)
  TOP w0.305: U1.82 41.73,27.76 v2(41.27,27.3) ; R5.1 v2(50.16,27.3) ; U1.45 42.24,14.03 41.66,14.61 v2(41.27,14.61) ; U10.7 v2(56.52,12.06)
  TOP w0.381: R6.1 v2(41.27,33.66) ; 48.9,21.85 v2(48.9,23.5) ; Y1.2 50.75,26.35 52.39,26.35 v2(52.7,26.04) ; 46.22,9.53 C32.2 46.92,10.16 ; C34.2 v2(50.8,31.11) ; v2(50.8,23.5) 50.8,23.11 50.16,22.48 U3.3 ; R27.1 v2(40.01,33.66) ; R1.1 v2(42.55,33.66) ; R2.1 v2(43.81,33.66) ; R4.1 v2(46.35,33.66) ; R3.1 v2(45.09,33.66)
  TOP w0.508: C28.2 49.66,25.27 Y1.2 ; C27.2 53.34,25.4 v2(52.7,26.04) ; U3.1 v2(52.7,23.5) ; 51.44,21.85 v2(51.44,20.32)
  BOTTOM w0.305: C74.2 v2(53.98,19.68) ; C11.2 41.41,27.44 v2(41.27,27.3)
  BOTTOM w0.381: v2(40.01,29.84) 39.87,29.71 C9.2 ; C6.1 45.22,25.9 v2(45.09,26.04) ; C78.2 C79.2 v2(59.05,20.95) ; C26.2 v2(52.7,12.06) ; C19.1 59.05,10.66 R16.1 v2(57.78,11.43) ; C13.2 v2(44.95,14.61) ; C72.2 v2(59.05,15.88) ; C75.2 v2(56.52,17.14) 57.15,16.51 C76.2 ; C73.2 v2(59.05,18.41) ; C64.2 v2(55.88,31.11) ; C65.2 v2(55.88,33.66) ; C77.2 v2(59.05,19.68) ; C71.2 v2(59.05,13.34)
  BOTTOM w0.508: C60.1 60.96,25.4 v2(60.33,24.77) ; v2(59.05,24.77) 59.69,25.4 C61.1 ; C1.1 45.22,22.36 v2(45.09,22.23) ; U9.4 v2(62.23,36.2) ; C2.1 36.33,27.44 v2(36.2,27.3) ; C3.1 39.87,27.44 v2(40.01,27.3)
  vias: v2(33.66,23.5) v2(34.92,31.11) v2(34.92,27.3) v2(34.92,26.04) v2(34.92,24.77) v2(34.92,23.5) v2(36.2,26.04) v2(36.2,24.77) v2(36.2,23.5) v2(37.47,26.04) v2(37.47,24.77) v2(37.47,23.5) v2(38.73,26.04) v2(38.73,24.77) v2(38.73,23.5) v2(38.73,22.23) v2(38.73,20.95) v2(38.73,19.68) v2(38.73,18.41) v2(38.73,17.14) v2(40.01,26.04) v2(40.01,24.77) v2(40.01,23.5) v2(40.01,22.23) v2(40.01,20.95) v2(40.01,19.68) v2(40.01,18.41) v2(40.01,17.14) v2(40.01,15.88) v2(40.01,14.61) v2(41.27,26.04) v2(41.27,24.77) v2(41.27,23.5) v2(41.27,22.23) v2(41.27,20.95) v2(41.27,19.68) v2(41.27,18.41) v2(41.27,17.14) v2(41.27,15.88) v2(42.55,26.04) v2(42.55,24.77) v2(42.55,23.5) v2(42.55,22.23) v2(42.55,20.95) v2(42.55,19.68) v2(42.55,18.41) v2(42.55,17.14) v2(42.55,15.88) v2(43.81,26.04) v2(43.81,24.77) v2(43.81,23.5) v2(43.81,22.23) v2(43.81,20.95) v2(43.81,19.68) v2(43.81,18.41) v2(43.81,17.14) v2(43.81,15.88) v2(44.45,0.76) v2(45.09,20.95) v2(45.09,19.68) v2(45.09,18.41) v2(45.09,17.14) v2(46.99,8.89) v2(46.99,0.76) v2(49.53,8.89) v2(49.53,0.76) v2(52.07,0.76) v2(52.7,46.23) v2(52.7,36.2) v2(52.7,27.3) v2(53.65,31.75) v2(54.61,0.76) v2(55.24,46.23) v2(55.24,9.53) v2(56.52,0.76) v2(57.78,46.23) v2(59.05,37.47) v2(59.11,32.69) v2(59.18,0.76) v2(60.33,46.23) v2(62.1,37.85) v2(62.23,32.38) v2(62.23,29.84) v2(62.36,46.23) v2(62.36,17.14) v2(62.36,14.61) v2(62.36,10.79) v2(62.36,8.26) v2(62.36,5.71) v2(62.36,3.17) v2(62.36,0.76)
VIN: length 39.3
  TOP w0.254: R119.2 v2(36.06,6.49) 35.95,6.49 33.62,4.15 22.91,4.15 20.08,6.99 v2(19.05,6.99)
  TOP w0.508: R160.2 v2(17.14,16.53) C41.1
  BOTTOM w0.254: v2(36.06,6.49) 37.43,6.49 D15.3 ; v2(17.14,16.53) 17.12,16.51 17.12,14.98 16.5,14.36 16.5,13.91 15.86,13.27 14.43,13.27 13.59,12.43 13.59,9.4 16.63,6.36 18.43,6.36 v2(19.05,6.99)
VIN+: length 7.7
  TOP w0.381: J1.16 21.59,41.68 21.59,39.33 22.88,38.04 R161.2 22.86,36.88 22.86,36.32
VIN-: length 7
  TOP w0.381: R47.2 20.32,38.61 19.05,39.88 19.05,41.68 J1.14
A_1.2V: length 6
  TOP w0.381: U2.16 17.75,5.99 17.91,5.84 17.91,5.21
A_3.3V: length 56.7
  TOP w0.254: U1.34 36.74,14.13 37.21,14.61 v2(37.47,14.61) ; v2(29.84,22.23) 30.12,21.95 U1.11
  TOP w0.381: 17.14,9.37 17.14,8.13 16.89,7.87 R12.1 ; v2(16.51,9.53) 16.51,8.89 16.26,8.64 14.1,8.64 13.49,9.25 U2.21
  TOP w0.508: R110.2 v2(32.38,33.55)
  TOP w0.635: v1(8.89,13.21) 15.91,13.21 16.73,12.39 16.73,10.67 17.24,10.16 17.85,10.16
  BOTTOM w0.381: v2(37.47,14.61) 37.33,14.47 C8.1 ; 26.99,44.13 26.67,43.81 26.67,41.15
  BOTTOM w0.508: v1(8.89,13.21) 8.38,12.7 5.99,12.7 5.36,12.08 4.32,12.08 R15.2 ; 26.99,44.13 28.32,45.47 34.16,45.47 36.83,42.8 38.13,42.8 40.71,45.38 47.83,45.38 R133.2 ; C7.1 v2(29.84,22.23)
  vias: v2(15.24,9.53)
CAN+: length 5.6
  BOTTOM w0.508: J5.2 66.67,6.86 R81.1 66.55,6.99 66.55,8.12 66.06,8.61 T2.3
CAN+5V: length 2.6
  TOP w0.508: C58.1 68.09,40.41 J2.11
CAN-: length 6
  BOTTOM w0.508: T2.2 68.56,8.66 68.07,8.17 R81.2 68.07,4.96 69.22,3.81
CAN_GND: length 9.3
  TOP w0.508: C58.2 68.29,42.95 J2.12 ; 67.56,28.46 C55.2 ; 67.56,28.46 C57.2 ; 67.56,28.46 v1(67.56,27.81) ; D7.1 67.13,22.35 v1(66.25,22.35)
  BOTTOM w0.508: v1(69.98,21.59) 71.12,21.59 71.54,22.01 D6.1 ; D5.1 v1(66.25,22.35)
  vias: v2(67.94,1.91) v2(68.67,32.78) v2(69.22,0.76) v2(70.48,45.09) v2(70.48,1.91) v2(71.75,43.81) v2(71.75,41.27) v2(71.75,10.79) v2(71.75,5.71) v2(71.75,3.17) v2(71.75,0.76) v2(72.26,45.09) v2(72.26,42.55) v2(72.26,40.01) v2(72.26,37.47) v2(72.26,34.92)
CANRX: length 25.9
  TOP w0.254: v2(40.01,31.11) 37.85,31.11 36.23,29.5 U1.93
  BOTTOM w0.254: R80.1 52.21,32.38 51.72,32.88 51.72,34.77 51.31,35.18 50.55,35.18 46.99,31.62 40.51,31.62 v2(40.01,31.11)
CANTX: length 16.3
  TOP w0.254: v2(52.27,33.15) 52.27,31.32 50.8,29.84 50.8,27.18 50.27,26.64 47.56,26.64 47.37,26.46 U1.74
  BOTTOM w0.254: v2(52.27,33.15) 52.88,33.15 54.66,34.92 R82.1
D_1.2V: length 10.2
  TOP w0.254: v2(45.09,24.77) 45.27,24.95 U1.71 ; U1.4 32.31,25.46 v2(32.38,25.53) ; U1.87 39.24,27.81 v2(38.73,27.3)
  TOP w0.305: U1.46 42.73,14.42 v2(42.55,14.61)
  BOTTOM w0.305: v2(32.38,25.53) 32.51,25.4 C4.2
  BOTTOM w0.381: v2(45.09,24.77) 45.22,24.9 C6.2 ; C5.2 42.41,14.47 v2(42.55,14.61)
  BOTTOM w0.508: C1.2 45.22,23.36 v2(45.09,23.5) ; C3.2 38.87,27.44 v2(38.73,27.3) ; C2.2 37.33,27.44 v2(37.47,27.3)
  vias: v2(43.18,8.89) v2(44.45,8.89)
D_3.3V: length 40.9
  TOP w0.254: v2(47.62,26.04) 47.54,25.95 U1.73 ; v2(47.62,23.5) 47.59,23.46 U1.68 ; U1.3 32.05,25.95 v2(32.38,26.29) ; U1.47 43.24,14.03 v2(43.81,14.61) ; U1.70 47.32,24.46 v2(47.62,24.77) ; U1.88 v2(38.73,29.84)
  TOP w0.305: v2(42.55,27.3) 42.73,27.49 U1.80
  TOP w0.381: U3.8 v2(52.7,14.61)
  TOP w0.508: R26.1 54.61,25.4 v2(53.98,26.04)
  GND03 w0.762: v2(61.59,24.77) 60.33,26.04 v2(53.98,26.04)
  BOTTOM w0.381: R20.2 R21.2 v2(50.16,12.06) R31.2 ; R19.2 R17.2 v2(53.98,11.43) ; R30.2 v2(48.9,12.06) ; R8.2 v2(47.62,12.06) 47.62,10.93 R22.2 ; C26.1 v2(52.7,14.61) ; C13.1 43.95,14.47 v2(43.81,14.61) ; R32.2 v2(51.44,12.06)
  BOTTOM w0.508: v2(61.59,24.77) 62.23,25.4 R73.1
  BOTTOM w0.762: 47.88,22.48 52.97,22.48 53.98,23.49 v2(53.98,26.04)
  vias: v2(46.35,12.7) v2(46.35,12.06)
FAULT: length 23.4
  TOP w0.254: J1.18 24.13,41.68 24.13,28.31 24.43,28.02 27.13,28.02 30.01,30.89 R38.1
II_U: length 1.3
  BOTTOM w0.508: R131.2 R64.1
II_V: length 46.7
  TOP w0.254: v1(26.96,29.28) 27.16,29.28 31.99,34.11 37.42,34.11 R132.1
  GND02 w0.254: v1(6.65,19.64) 6.65,19.58 9.55,16.68 13.55,16.68 14.36,17.49 v1(14.36,18.06)
  BOTTOM w0.254: R65.1 5.97,20.32 v1(6.65,19.64) ; v1(26.96,29.28) 26.4,29.84 24.49,29.84 23.88,29.23 23.88,27.66 23.42,27.2 23.42,24.66 23.01,24.26 23.01,19.38 21.96,18.33 14.63,18.33 v1(14.36,18.06)
II_W: length 55.8
  TOP w0.254: v1(36.88,34.88) 36.54,34.54 31.57,34.54 27.21,30.17 v1(26.93,30.17)
  GND02 w0.254: v1(9.53,21.21) 8.77,20.45 8.77,18 9.65,17.11 13.16,17.11 13.68,17.64 13.68,18.21 v1(14.32,18.86)
  BOTTOM w0.254: v1(36.88,34.88) 39.19,34.88 R134.1 ; v1(14.32,18.86) 21.58,18.86 22.56,19.83 22.56,28.84 24.01,30.29 26.81,30.29 v1(26.93,30.17) ; v1(9.53,21.21) 10.16,21.85 10.16,25.54 R130.1
IPH_U: length 26.3
  TOP w0.254: v2(31.75,36.2) 30.65,36.2 24.66,30.2 v2(24.66,29.32) ; R106.2 C95.2 37.47,39.37 v2(36.83,38.73)
  BOTTOM w0.254: v2(31.75,36.2) 33.66,38.1 36.2,38.1 v2(36.83,38.73) ; v2(24.66,29.32) 25.22,28.76 25.22,25.11 D16.3 25.87,23.8 R121.2
IPH_U+: length 13.7
  TOP w0.381: R108.2 36.19,43.05 35.69,43.05 33.66,45.09 30.61,45.09 29.21,43.69 29.21,41.68 J1.21
  TOP w0.508: R108.2 37.47,43.04 R111.2
IPH_U-: length 11.2
  TOP w0.381: J1.23 30.48,41.24 31.75,42.51 31.75,44.07 32.13,44.45 33.4,44.45 35.81,42.05 R108.1
  TOP w0.508: R55.2 37.56,42.05 37.1,42.05 37.08,42.07 36.56,42.07 36.54,42.05 R108.1
IPH_V: length 52.6
  TOP w0.254: v2(24.63,28.61) 25.7,28.61 26.35,29.26 26.35,30.5 30.78,34.92 35.81,34.92 36.06,35.18 C100.2 R138.2 ; R126.2 29.06,5.73 28.43,5.1 23.68,5.1 20.29,8.49 20.29,13.49 v1(20.66,13.86)
  BOTTOM w0.254: v2(24.63,28.61) 24.74,28.5 24.74,24.59 24.08,23.93 24.08,17.28 v1(20.66,13.86)
  BOTTOM w0.305: 24.08,18.59 25.7,18.59 26.2,18.08 D17.3
IPH_V+: length 5.6
  TOP w0.381: R112.2 35.52,37.96 33.08,40.41 J1.25
  TOP w0.508: R112.2 37.47,37.96 R141.2
IPH_V-: length 10.7
  TOP w0.381: J1.26 33.02,42.29 31.75,41.02 31.75,39.88 32.64,38.99 33.66,38.99 35.68,36.97 R112.1
  TOP w0.508: R112.1 37.47,36.97 R143.2
IPH_W: length 28.8
  TOP w0.254: v2(33.02,36.2) 32.38,35.56 30.71,35.56 25.63,30.48 v2(25.63,29.35)
  BOTTOM w0.254: R115.2 26.2,19.86 D18.3 26.2,21.86 27.18,22.83 27.18,24.64 26.67,25.15 26.67,25.75 27.21,26.29 27.21,27.77 v2(25.63,29.35) ; R146.2 C106.2 36.96,36.83 36.58,37.21 33.78,37.21 33.02,36.45 v2(33.02,36.2)
IPH_W+: length 13.7
  BOTTOM w0.381: J1.22 29.78,44.79 33.91,44.79 34.85,43.85 34.85,41.37 35.71,40.5 R113.2
  BOTTOM w0.508: R113.2 37.47,40.5 37.58,40.62 R149.2
IPH_W-: length 11.1
  BOTTOM w0.381: J1.24 31.73,44.2 33.66,44.2 34.23,43.62 34.23,41.08 35.81,39.51 R113.1
  BOTTOM w0.508: R113.1 37.47,39.51 R151.2
IU: length 52.8
  TOP w0.254: R154.1 v2(31.11,5.72)
  BOTTOM w0.254: R153.1 C37.1 2.02,26.54 1.4,25.91 1.4,18.29 2.1,17.59 7.12,17.59 10.16,14.55 10.16,12.06 10.79,11.43 10.79,7.62 15.1,3.31 21.6,3.31 22.75,4.47 29.87,4.47 v2(31.12,5.72) D12.3
IU+: length 5.8
  BOTTOM w0.508: R49.1 6.85,35.56 R44.1 6.85,37.12 5.08,38.89 J1.3
IU-: length 6.4
  BOTTOM w0.508: J1.1 5.85,37.1 R44.2 5.85,35.56 R42.1
IV: length 33.6
  TOP w0.254: v2(26.04,6.99) 25.54,6.49 R157.1
  BOTTOM w0.254: R159.1 8.25,20.46 C39.1 8.26,17.91 11.18,14.99 11.18,12.7 11.68,12.19 11.68,8.26 15.61,4.33 20.71,4.33 23.29,6.9 24.38,6.9 D13.3 25.57,6.52 v2(26.04,6.99)
IV+: length 5.8
  BOTTOM w0.508: R52.1 11.93,35.56 R50.1 11.93,37.6 10.16,39.37 J1.7
IV-: length 6.7
  BOTTOM w0.508: R46.1 10.93,35.56 R50.2 10.93,37.58 8.1,40.41 J1.5
IW: length 48.5
  TOP w0.254: v2(21.71,6.17) 23.27,4.62 33.19,4.62 v2(34.29,5.72) R156.2
  BOTTOM w0.152: D14.3 v2(34.29,5.72)
  BOTTOM w0.254: v2(21.71,6.17) 20.38,4.84 15.86,4.84 12.16,8.54 12.16,12.48 11.68,12.95 11.68,15.37 9.53,17.53 9.53,19.94 10.79,21.21 10.79,23.24 13.2,25.65 C49.1 13.2,27.31 R58.1
IW+: length 5.8
  BOTTOM w0.508: J1.11 15.24,39.37 17.01,37.6 R61.1 17.01,35.56 R62.1
IW-: length 6.7
  BOTTOM w0.508: R59.1 16.01,35.56 R61.2 16.01,37.6 13.2,40.41 J1.9
LED_RED: length 4.2
  TOP w0.254: U1.94 35.74,29.77 36.83,30.86 36.83,31.82 D1.1
MCU_X1: length 3.6
  TOP w0.254: Y1.3 49.66,24.26 C28.1 47.68,24.26 47.37,23.95 U1.69
NETC25_1: length 6.6
  TOP w0.381: U2.7 4.57,7.29 4.4,7.12 C25.1
  TOP w0.508: C25.1 R11.1 2.04,7.12 v2(1.91,6.99)
  BOTTOM w0.508: Q1.3 2.07,7.15 v2(1.91,6.99)
NETC27_1: length 3
  TOP w0.508: R26.2 54.61,24.26 C27.1 51.94,24.26 Y1.4
NETC35_1: length 18.1
  TOP w0.508: IC1.3 70.57,31.77 71.12,31.22 71.12,21.54 68.58,19 R34.1 68.58,18.41 C35.1 67.31,18.41 R35.2
NETC36_1: length 5.1
  BOTTOM w0.508: U5.8 4.45,22.61 3.68,21.84 C36.1 C91.2 3.68,19.05 R150.1
NETC38_1: length 6.9
  BOTTOM w0.508: R64.2 R153.2 4.08,29.1 U5.1 4.58,29.6 C38.1 R40.2
NETC38_2: length 5.1
  BOTTOM w0.508: R42.2 5.71,33.16 R40.1 C38.2 5.71,31.62 U5.2
NETC40_1: length 15.1
  BOTTOM w0.508: R159.2 R65.2 5.71,21.71 U5.7 5.71,26.16 7.63,28.07 8.78,28.07 9.08,28.37 9.08,28.39 9.27,28.58 9.27,30.06 9.66,30.45 R43.2 C40.1
NETC40_2: length 12.8
  BOTTOM w0.508: R46.2 10.79,33.15 C40.2 R43.1 10.59,31.68 10.59,29.64 10.29,29.34 10.29,28.45 9.12,27.28 8,27.28 6.99,26.26 U5.6
NETC42_2: length 5.6
  TOP w0.508: U4.5 22.23,25.3 22.36,25.43 C42.2 R41.1 22.36,28.58 R39.2
NETC43_1: length 10.1
  TOP w0.508: R45.2 C43.1 19.82,25.05 19.68,24.92 U4.7 19.68,21.39 17.14,18.85 R160.1
NETC43_2: length 5.6
  TOP w0.508: R48.1 20.82,28.58 R45.1 C43.2 20.82,25.05 20.95,24.92 U4.6
NETC44_2: length 5.1
  BOTTOM w0.508: U5.3 6.99,31.62 C44.2 R51.1 6.99,33.16 R49.2
NETC45_2: length 12.3
  BOTTOM w0.508: 8.26,23.87 8.26,25.17 11.23,28.14 11.23,28.87 11.3,28.95 11.3,28.97 11.6,29.27 11.62,29.27 12.2,29.84 C45.2 R53.1 12.06,33.16 R52.2
NETC48_1: length 6.9
  BOTTOM w0.508: R130.2 R58.2 14.09,28.44 14.61,28.96 14.61,29.47 14.74,29.6 C48.1 R57.2
NETC48_2: length 5.1
  BOTTOM w0.508: R59.2 15.88,33.16 R57.1 C48.2 15.88,31.62 U6.2
NETC50_1: length 5
  BOTTOM w0.508: R60.1 15.88,21.45 C92.1 C50.1 14.61,23.87
NETC51_2: length 5.1
  BOTTOM w0.508: 17.14,29.47 17.14,31.62 C51.2 R63.1 17.14,33.16 R62.2
NETC52_1: length 0.8
  TOP w0.508: C52.1 v1(50.16,42.55)
NETC53_1: length 4.4
  TOP w0.508: U7.8 3.81,24.13 v2(3.17,24.77) ; R66.1 2.54,25.4 v2(3.17,24.77) ; v2(3.17,24.77) 2.54,24.13 C93.1
  BOTTOM w0.508: C93.1 2.54,24.13 v2(3.17,24.77)
NETC54_2: length 6
  TOP w0.508: U7.5 7.62,24.43 6.48,25.56 C54.2 6.48,27.3 R68.1 6.49,28.58 R70.1
NETC59_1: length 6.1
  TOP w0.508: U7.6 6.35,24.63 C59.1 4.95,27.3 R74.2 4.94,28.58 R72.1
NETC59_2: length 6.4
  TOP w0.508: v2(5.08,22.23) U7.7 5.08,24.51 3.94,25.65 C59.2 3.94,27.3 R74.1
  BOTTOM w0.508: R67.2 4.83,21.97 v2(5.08,22.23)
NETC62_2: length 5.6
  TOP w0.508: R79.1 10.66,28.58 R77.1 C62.2 10.66,25.28 10.79,25.15 U8.3
NETC64_1: length 3.8
  BOTTOM w0.254: R80.2 C64.1 U9.2
NETC65_1: length 3.8
  BOTTOM w0.254: R82.2 C65.1 U9.3
NETC66_1: length 5.6
  TOP w0.508: U8.2 12.06,25.9 C66.1 R85.2 12.2,28.58 R84.1
NETC66_2: length 6.2
  TOP w0.508: v2(12.7,22.23) 13.34,22.86 13.34,25.27 13.2,25.41 C66.2 R85.1
  BOTTOM w0.508: R76.2 v2(12.7,22.23)
NETC67_2: length 15
  TOP w0.508: R90.1 15.74,28.58 R88.1 C67.2 15.74,23.87 13.23,21.36 10.98,21.36 9.53,19.9 U8.5
NETC68_1: length 5
  TOP w0.508: R86.1 15.87,15.74 C68.1 C104.1 13.34,18.15
NETC70_1: length 15.2
  TOP w0.508: R92.1 17.28,28.58 R93.2 C70.1 16.51,25.27 16.51,23.5 13.51,20.49 11.35,20.49 10.68,19.83 10.68,19.03 10.79,18.92 U8.6
NETC70_2: length 13.7
  TOP w0.508: R93.1 C70.2 18.28,25.65 17.27,24.64 17.27,23.11 13.84,19.68 v2(12.2,19.68) 12.06,19.55 U8.7
  BOTTOM w0.508: R87.2 12.7,19.19 v2(12.2,19.68)
NETC71_1: length 4.1
  TOP w0.381: U10.9 v2(62.23,13.34)
  BOTTOM w0.254: R96.2 60.83,12.07 C71.1 v2(62.23,13.34)
NETC72_1: length 4.1
  TOP w0.381: U10.11 v2(62.23,15.88)
  BOTTOM w0.254: R99.2 60.83,14.61 C72.1 v2(62.23,15.88)
NETC73_1: length 4.1
  TOP w0.381: U10.13 v2(62.23,18.41)
  BOTTOM w0.254: v2(62.23,18.41) C73.1 60.83,17.15 R103.2
NETC74_1: length 3.3
  TOP w0.381: U10.1 v2(56.52,19.68)
  BOTTOM w0.254: v2(56.52,19.68) C74.1 55.74,19.69 R105.1
NETC75_1: length 3.3
  TOP w0.254: U10.3 v2(53.98,17.14)
  BOTTOM w0.254: R101.2 54.75,17.15 C75.1 v2(53.98,17.14)
NETC76_1: length 3.9
  TOP w0.305: U10.5 v2(56.52,14.61)
  BOTTOM w0.254: C76.1 57.15,15.24 v2(56.52,14.61) 55.74,15.38 R98.2
NETC77_1: length 6.7
  TOP w0.559: U10.14 v2(62.23,19.68)
  BOTTOM w0.559: v2(62.23,19.68) C77.1 C79.1 C78.1 60.82,22.23 R109.2
NETC80_1: length 2.8
  TOP w0.254: R119.1 C80.1 38.1,9.02 R118.2
NETC81_1: length 1.5
  BOTTOM w0.254: v1(24.84,21.06) 24.84,19.67 R115.1
NETC82_1: length 6.3
  TOP w0.254: U1.24 30.31,15.45 29.84,14.98 29.84,14.22 27.86,12.24 26.59,12.24 C82.1
NETC83_1: length 6.6
  TOP w0.254: U1.25 30.56,14.96 30.3,14.7 30.3,13.79 28.3,11.79 27.28,11.79 26.67,11.18 C83.1
NETC84_1: length 2.3
  TOP w0.254: R129.2 22.89,10.91 C84.1 22.88,9.7 R128.1
NETC85_1: length 3.3
  TOP w0.254: R127.2 29.21,9.02 C85.1 27.94,8.69 29.06,7.57 R126.1
NETC86_1: length 1.8
  BOTTOM w0.305: v1(24.84,17.96) 24.84,16.45 R125.1
NETC87_1: length 2.9
  TOP w0.254: R122.2 C87.1 38.1,7.49 38.09,7.48 R123.1
NETC88_1: length 1.2
  TOP w0.254: v1(24.81,23.47) 24.84,23.75 IU.1
  BOTTOM w0.152: R121.1 24.87,23.41 v1(24.81,23.47)
NETC89_1: length 5.1
  TOP w0.508: U4.8 18.41,22.86 v2(19.05,22.23)
  BOTTOM w0.508: v2(19.05,22.23) C113.1 C89.1 20.32,21.45 R148.1
NETC90_1: length 6.2
  TOP w0.254: R38.2 31.11,31.89 31.11,31.89 R110.1 32.39,31.88 C90.1 33.66,31.07 32.74,30.15 U1.100
NETC94_2: length 8.4
  TOP w0.508: U11.3 43.81,44.71 43.14,45.38 41.6,45.38 41.27,45.05 C94.2 40.01,44.32 R107.1 39.24,44.31 38.6,43.68 R111.1
NETC96_1: length 8.6
  TOP w0.508: U11.2 45.09,42.16 44.08,41.15 42.19,41.15 41.74,41.6 41.71,41.6 41.53,41.78 C96.1 41.27,41.77 R136.2 39.69,42.09 R55.1
NETC96_2: length 63.1
  TOP w0.508: 40.01,40.77 R136.1 ; 40.01,40.77 C96.2 41.79,40.26 44.23,40.26 46.35,42.38 U11.1 ; 40.01,40.77 39.87,40.64 38.62,40.64 R106.1 v1(38.6,41.32)
  GND02 w0.508: v1(38.6,41.32) 38.6,43.09 v1(37.52,44.17)
  BOTTOM w0.508: v1(37.52,44.17) 35.49,46.21 27.61,46.21 26.3,44.89 1.82,44.89 1.23,44.3 1.23,38.78 2.54,37.47 R131.1
NETC97_1: length 4.7
  TOP w0.508: R137.1 C99.1 C97.1 46.74,36.83 46.35,37.21 U11.8
NETC98_2: length 4.2
  TOP w0.508: R141.1 38.73,38.23 C98.2 40.01,38.24 R139.1 42.26,38.24 42.55,37.95 U11.5
NETC101_1: length 6.6
  TOP w0.508: R143.1 39.87,36.83 R144.2 41.27,36.69 C101.1 41.76,36.7 42.02,36.44 43.55,36.44 43.81,36.7 U11.6
NETC101_2: length 9.2
  TOP w0.508: U11.7 45.09,36.96 43.82,35.69 C101.2 40.01,35.69 R144.1 39.87,35.56 R138.1 R132.2
NETC102_1: length 4.6
  BOTTOM w0.508: U12.8 48.64,38.1 48.26,37.72 C105.1 C102.1 46.99,36.69 R145.1
NETC103_2: length 5.1
  BOTTOM w0.508: R149.1 38.61,40.63 38.86,40.63 38.87,40.64 39.87,40.64 R147.1 41.27,40.78 C103.2 41.41,40.64 U12.3
NETC107_1: length 5.1
  BOTTOM w0.508: U12.2 43.42,39.24 C107.1 40.01,39.24 R152.2 38.73,39.23 R151.1
NETC107_2: length 6.6
  BOTTOM w0.508: R146.1 38.73,38.24 R152.1 ; R152.1 R134.2 ; R152.1 41.27,38.24 C107.2 43.42,38.23 U12.1
NETC108_1: length 2.8
  TOP w0.254: R156.1 C108.1 35.56,9.02 R114.2
NETC109_1: length 2.8
  TOP w0.254: R157.2 C109.1 24.77,9.03 R158.1
NETC110_1: length 2.8
  TOP w0.254: R154.2 C110.1 32.38,9.02 R155.1
NETD1_2: length 1.6
  TOP w0.381: D1.2 38.97,31.89 R27.2
NETD2_2: length 1.3
  TOP w0.381: D2.2 17.94,12.52 R28.2
NETD3_1: length 14.5
  BOTTOM w0.508: U9.7 70.5,31.11 71.01,30.61 71.01,27.69 70.5,27.18 69.64,27.18 68.63,26.17 68.63,25.03 D3.1 D5.2 68.23,22.86 T1.4
NETD3_2: length 7.4
  TOP w0.508: v1(66.25,26.04) 67.77,26.04 D7.2 69.8,26.09 v1(70.1,25.78)
  BOTTOM w0.508: D3.2 v1(66.25,26.04) ; v1(70.1,25.78) 70.99,25.78 71.54,25.23 D4.2
